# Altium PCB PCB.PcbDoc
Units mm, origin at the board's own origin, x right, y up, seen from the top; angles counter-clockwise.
Board outline 152.4 x 101.6 mm, 2 copper layers (Top Layer, Bottom Layer); 28 components, 28 nets, 134 pads, 40 vias.
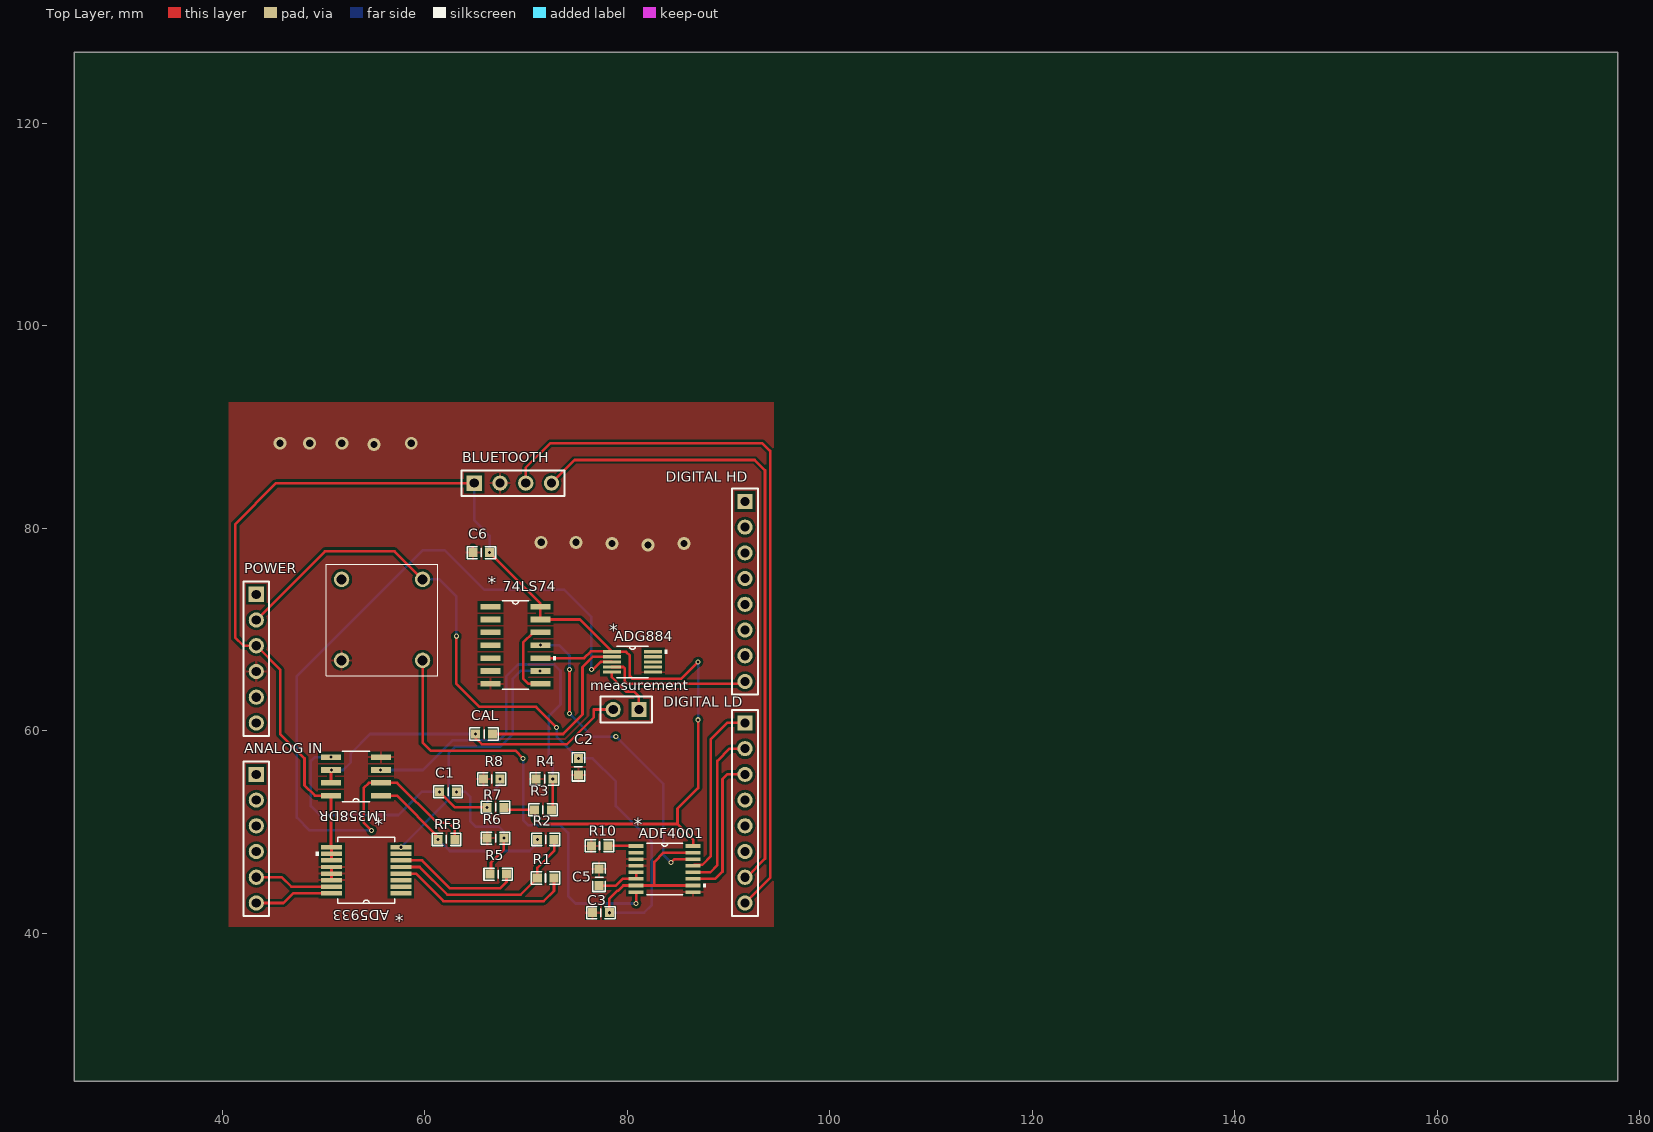
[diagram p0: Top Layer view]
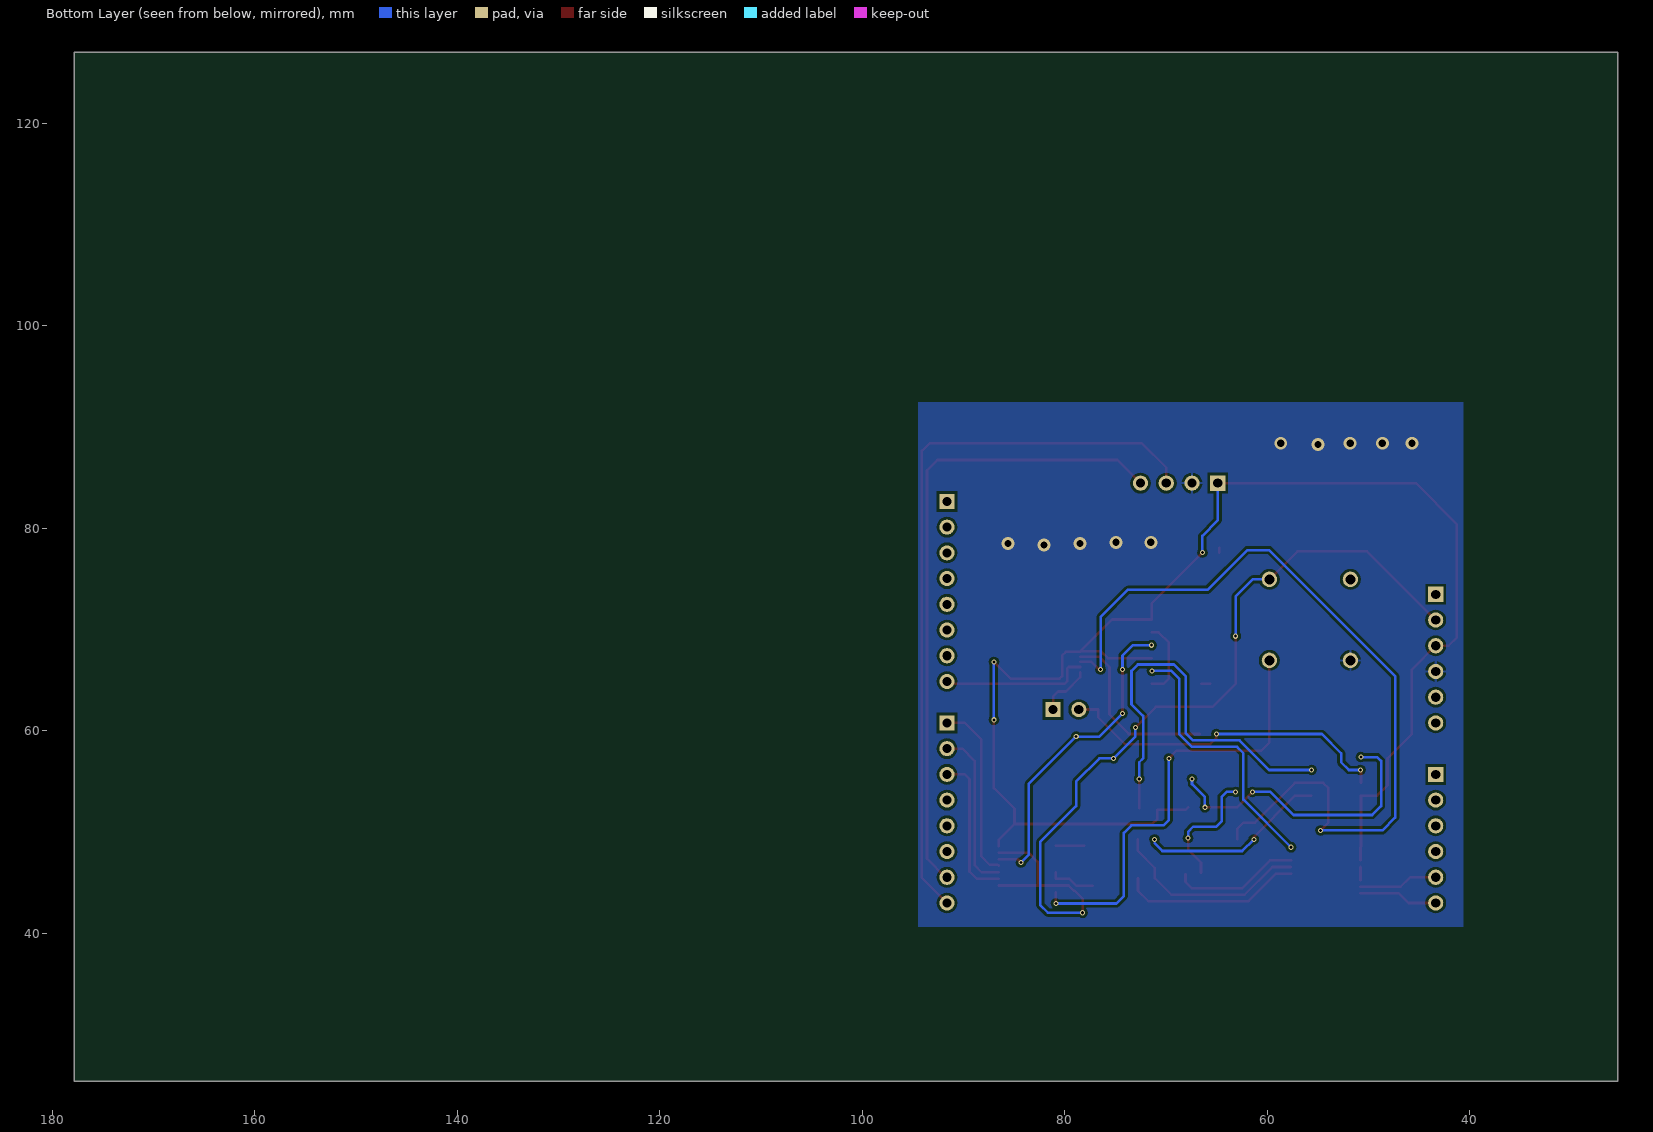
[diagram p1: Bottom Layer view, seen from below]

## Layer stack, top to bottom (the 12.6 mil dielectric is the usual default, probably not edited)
Top Solder: solder mask 0.0102, Solder Resist, Dk 3.5
Top Layer: signal copper 0.0356
Dielectric 1: dielectric 0.32, FR-4, Dk 4.8
Bottom Layer: signal copper 0.0356
Bottom Solder: solder mask 0.0102, Solder Resist, Dk 3.5

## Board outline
25.4,25.4 177.8,25.4 177.8,127 25.4,127

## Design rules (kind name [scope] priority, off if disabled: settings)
Clearance [All] p1: gap=0.254
PolygonConnect [All] p1: connectstyle=Relief reliefconductorwidth=0.254 reliefentries=4 polygonreliefangle="90 Angle" airgapwidth=0.254
RoutingVias [All] p1: holewidth=0.711 width=1.27 viastyle="Through Hole" minholewidth=0.711 minwidth=1.27 maxholewidth=0.711 maxwidth=1.27
SolderMaskExpansion [All] p1: expansion=0.102
Width [All] p1: maxlimit=0.254 minlimit=0.254 preferedwidth=0.254
29 further rules are at their usual default settings.

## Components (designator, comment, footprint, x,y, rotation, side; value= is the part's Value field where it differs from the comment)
74LS74 "SN74LS74A_D_14" D14 68.961,68.453 r0 top
AD5933 "AD5933YRSZ" RS_16 54.229,46.228 r180 top
ADF4001 "ADF4001BRUZ" RU_16 83.693,46.355 r0 top
ADG884 "ADG884BRMZ" RM_10 80.518,66.802 r0 top
"ANALOG IN" "MHDR1X6" "XH2.54Z P6" 43.37,55.7 r270 top
BLUETOOTH "MHDR1X4" "XH2.54Z P4" 64.897,84.455 r0 top
C1 "Cap Pol1" 0603 61.468,53.975 r0 top
C2 "Cap Pol1" 0603 75.184,57.277 r270 top
C3 "Cap Pol1" 0603 78.232,42.037 r180 top
C5 "Cap Pol1" 0603 77.216,44.704 r90 top
C6 "Cap Pol1" 0603 66.421,77.597 r180 top
CAL "Res3" 0603 65.024,59.69 r0 top (schematic designator R9)
"DIGITAL HD" "MHDR1X8" "XH2.54Z P8" 91.63,82.652 r270 top
"DIGITAL LD" "MHDR1X8" "XH2.54Z P8" 91.63,60.78 r270 top
LM358DR "LM358_D_8" D8 53.213,55.499 r180 top
measurement "PROBE" "XH2.54Z P2" 81.153,62.103 r180 top
POWER "MHDR1X6" "XH2.54Z P6" 43.37,73.48 r270 top
R1 "Res3" 0603 72.771,45.466 r180 top
R2 "Res3" 0603 71.12,49.276 r0 top
R3 "Res3" 0603 72.517,52.197 r180 top
R4 "Res3" 0603 70.993,55.245 r0 top
R5 "Res3" 0603 66.421,45.847 r0 top
R6 "Res3" 0603 66.167,49.403 r0 top
R7 "Res3" 0603 66.167,52.451 r0 top
R8 "Res3" 0603 65.786,55.245 r0 top
R10 "Res3" 0603 78.105,48.641 r180 top
RFB "Res3" 0603 62.992,49.276 r180 top
? "CRYSTAL" CRYSTAL 50.292,76.454 r270 top

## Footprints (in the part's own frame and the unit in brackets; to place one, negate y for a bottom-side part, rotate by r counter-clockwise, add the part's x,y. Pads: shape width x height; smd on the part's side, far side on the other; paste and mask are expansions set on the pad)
0603 [mil]
  rect 35x35 smd: 1(0.27,0) 2(65.27,0)
  silkscreen extent -22,-24 88,24
CRYSTAL [mm] "2.048MHz"
  round 1.524 hole 1: 1(1.5,9.5) 2(1.5,1.5) 3(9.5,1.5) 4(9.5,9.5)
  silkscreen extent 0,0 11,11
D8 [mil]
  rect 78x22 smd: 1(-97,75) 2(-97,25) 3(-97,-25) 4(-97,-75) 5(97,-75) 6(97,-25) 7(97,25) 8(97,75)
  silkscreen extent -54,-98 54,98
D14 [mil]
  rect 78x22 smd: 1(-97,150) 2(-97,100) 3(-97,50) 4(-97,0) 5(-97,-50) 6(-97,-100) 7(-97,-150) 8(97,-150) 9(97,-100) 10(97,-50) 11(97,0) 12(97,50) 13(97,100) 14(97,150)
  silkscreen extent -51,-172 156,172
RM_10 [mil]
  rect 70x13 smd mask+4: 1(-80.5,39.37) 2(-80.5,19.68) 3(-80.5,0) 4(-80.5,-19.68) 5(-80.5,-39.37) 6(80.5,-39.37) 7(80.5,-19.68) 8(80.5,0) 9(80.5,19.68) 10(80.5,39.37)
  silkscreen extent -61,-61 136,61
RS_16 [mil]
  rect 81x17 smd: 1(-135,89.57) 2(-135,63.98) 3(-135,38.39) 4(-135,12.8) 5(-135,-12.8) 6(-135,-38.39) 7(-135,-63.98) 8(-135,-89.57) 9(135,-89.57) 10(135,-63.98) 11(135,-38.39) 12(135,-12.8) 13(135,12.8) 14(135,38.39) 15(135,63.98) 16(135,89.57)
  silkscreen extent -110,-128 196,128
RU_16 [mil]
  rect 58x14 smd mask+4: 1(-111,89.57) 2(-111,63.98) 3(-111,38.39) 4(-111,12.8) 5(-111,-12.8) 6(-111,-38.39) 7(-111,-63.98) 8(-111,-89.57) 9(111,-89.57) 10(111,-63.98) 11(111,-38.39) 12(111,-12.8) 13(111,12.8) 14(111,38.39) 15(111,63.98) 16(111,89.57)
  silkscreen extent -70,-100 160,100
"XH2.54Z P2" [mm] "Connector; Header; 6 Position"
  rect 1.5x1.5 hole 0.9: 1(0,0)
  round 1.5 hole 0.9: 2(2.54,0)
  silkscreen extent -1.27,-1.27 3.81,1.27
"XH2.54Z P4" [mm] "Connector; Header; 6 Position"
  rect 1.5x1.5 hole 0.9: 1(0,0)
  round 1.5 hole 0.9: 2(2.54,0) 3(5.08,0) 4(7.62,0)
  silkscreen extent -1.27,-1.27 8.89,1.27
"XH2.54Z P6" [mm] "Connector; Header; 6 Position"
  rect 1.5x1.5 hole 0.9: 1(0,0)
  round 1.5 hole 0.9: 2(2.54,0) 3(5.08,0) 4(7.62,0) 5(10.16,0) 6(12.7,0)
  silkscreen extent -1.27,-1.27 13.97,1.27
"XH2.54Z P8" [mm] "Connector; Header; 6 Position"
  rect 1.5x1.5 hole 0.9: 1(0,0)
  round 1.5 hole 0.9: 2(2.54,0) 3(5.08,0) 4(7.62,0) 5(10.16,0) 6(12.7,0) 7(15.24,0) 8(17.78,0)
  silkscreen extent -1.27,-1.27 19.05,1.27

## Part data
74LS74 AD5933 ADF4001 ADG884 LM358DR: "Imported"
"ANALOG IN" POWER: "Header, 6-Pin"
BLUETOOTH: "Header, 4-Pin"
C1 C2 C3 C5 C6: "Polarized Capacitor (Radial)"
CAL R1 R2 R3 R4 R5 R6 R7 R8 R10 RFB: "Resistor"
"DIGITAL HD" "DIGITAL LD": "Header, 8-Pin"
measurement: library part MHDR1X2, "Header, 2-Pin"

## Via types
v1: diameter 0.5, hole 0.3, Top Layer to Bottom Layer, 30 vias
v2: diameter 1.27, hole 0.711, Top Layer to Bottom Layer, 10 vias

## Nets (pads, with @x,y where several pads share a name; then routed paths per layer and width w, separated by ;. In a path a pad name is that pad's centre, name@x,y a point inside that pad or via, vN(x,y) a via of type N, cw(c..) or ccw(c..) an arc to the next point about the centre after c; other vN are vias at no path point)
GND: 74LS74.7 ?.3 AD5933.12 AD5933.13 AD5933.14 ADF4001.3 ADF4001.4 ADF4001.9 ADG884.6 BLUETOOTH.2 C2.2 C3.2 C5.2 C6.2 LM358DR.4 POWER.4 R4.1 R6.1 R8.1 R10.2 | length 3.7
  Top Layer w0.254: POWER.4@42.873,65.86 POWER.4 ; AD5933.14 AD5933.13 AD5933.12 ; ?.3 ?.3@52.349,66.954 ; C6.2 64.763,78.098 ; 74LS74.7@65.659,64.643 74LS74.7
  other v2: 82.042,78.359 78.486,78.486 85.598,78.486 71.501,78.613 74.93,78.613 54.991,88.265 45.72,88.392 48.641,88.392 51.816,88.392 58.674,88.392
Net74LS74_8: 74LS74.8 74LS74.12 | length 7.6
  Top Layer w0.254: 74LS74.8 70.231,64.643 69.723,65.151 69.723,68.707 70.739,69.723 74LS74.12
Net74LS74_9: 74LS74.9 AD5933.8 | length 26.8
  Bottom Layer w0.254: v1(57.658,48.503) 62.357,53.202 62.357,57.785 62.992,58.42 67.437,58.42 68.707,59.69 68.707,65.151 69.469,65.913 v1(71.374,65.913)
Net74LS74_11: 74LS74.11 ADF4001.14 | length 31.6
  Top Layer w0.254: v1(74.295,61.722) v1(74.295,66.04) ; v1(84.328,46.99) 84.668,47.33 ADF4001.14
  Bottom Layer w0.254: v1(71.425,68.453) 73.279,68.453 74.295,67.437 v1(74.295,66.04) ; v1(74.295,61.722) 76.581,59.436 v1(78.867,59.436) 83.566,54.737 83.566,47.752 v1(84.328,46.99)
Net_1: ?.1 ADF4001.7 ADF4001.10 ADF4001.15 C2.1 C3.1 POWER.2 | length 88.2
  Top Layer w0.254: POWER.2 50.154,77.724 57.022,77.724 ?.1 ; v1(63.119,69.342) 63.119,64.643 65.405,62.357 70.993,62.357 v1(73.025,60.325) ; C3.1 78.225,43.427 79.001,44.203 79.084,44.203 79.611,44.73 ADF4001.7 82.677,44.73 ; ADF4001.10 82.677,44.73 ; ADF4001.15 83.592,47.98 82.677,47.065 82.677,44.73
  Bottom Layer w0.254: ?.1 61.444,74.954 63.119,73.279 v1(63.119,69.342) ; v1(73.025,60.325) 73.025,59.436 v1(75.184,57.277) 76.581,57.277 78.867,54.991 78.867,52.578 82.423,49.022 82.423,42.799 81.661,42.037 v1(78.232,42.037)
Net_4: ?.4 ADF4001.8 | length 44.1
  Top Layer w0.254: ?.4 59.792,58.826 60.579,58.039 68.961,58.039 v1(69.723,57.277) ; v1(80.874,42.951) ADF4001.8
  Bottom Layer w0.254: v1(69.723,57.277) 69.723,51.181 70.231,50.673 73.406,50.673 74.168,49.911 74.168,43.688 74.905,42.951 v1(80.874,42.951)
NetAD5933_4: AD5933.4 R1.1 | length 17.9
  Top Layer w0.254: AD5933.4 59.126,45.903 61.849,43.18 71.755,43.18 72.764,44.189 R1.1
NetAD5933_5: AD5933.5 R1.2 R2.2 | length 19.8
  Top Layer w0.254: AD5933.5 59.492,46.553 62.23,43.815 69.462,43.815 R1.2 71.113,46.475 72.778,48.14 R2.2
NetAD5933_6: AD5933.6 R5.2 | length 12.6
  Top Layer w0.254: AD5933.6 59.731,47.203 62.484,44.45 67.437,44.45 68.079,45.092 R5.2
NetAD5933_15: "ANALOG IN.5" AD5933.15 | length 7.8
  Top Layer w0.254: 43.37,45.54 45.9,45.54 46.837,44.603 AD5933.15
NetAD5933_16: "ANALOG IN.6" AD5933.16 | length 7.8
  Top Layer w0.254: 43.37,43 46.048,43 47.001,43.953 AD5933.16
NetADF4001_1: ADF4001.1 R10.1 | length 2.8
  Top Layer w0.254: R10.1 ADF4001.1@80.863,48.641
NetADF4001_5: ADF4001.5 ADF4001.6 C5.1 | length 4.6
  Top Layer w0.254: C5.1 78.874,44.711 79.543,45.38 ADF4001.6 ADF4001.5
NetADF4001_11: "DIGITAL LD.3" ADF4001.11 | length 14.7
  Top Layer w0.254: ADF4001.11 88.687,45.38 89.408,46.101 89.408,55.245 89.863,55.7 91.63,55.7
NetADF4001_12: "DIGITAL LD.2" ADF4001.12 | length 16.2
  Top Layer w0.254: ADF4001.12 88.194,46.03 88.9,46.736 88.9,57.023 90.117,58.24 91.63,58.24
NetADF4001_13: "DIGITAL LD.1" ADF4001.13 | length 17.7
  Top Layer w0.254: ADF4001.13 86.604,46.771 87.407,46.771 88.265,47.629 88.265,59.182 89.863,60.78 91.63,60.78
NetADG884_2: ADG884.2 CAL.2 | length 17.7
  Top Layer w0.254: CAL.2 73.66,59.69 75.581,61.611 75.581,66.294 76.589,67.302 ADG884.2
NetADG884_3: ADG884.3 LM358DR.2 RFB.1 | length 83
  Top Layer w0.254: v1(54.737,50.165) 53.975,50.927 53.975,54.356 54.483,54.864 LM358DR.2 57.277,54.864 61.214,50.927 62.357,50.927 62.985,50.299 RFB.1 ; v1(76.454,66.04) 76.618,66.04 77.372,66.794 ; 77.38,66.802 ADG884.3
  Bottom Layer w0.254: v1(54.737,50.165) 48.641,50.165 47.371,51.435 47.371,65.405 59.817,77.851 61.976,77.851 65.913,73.914 73.787,73.914 76.454,71.247 v1(76.454,66.04)
NetADG884_4: "DIGITAL HD.8" ADG884.4 | length 14.7
  Top Layer w0.254: ADG884.4 79.621,66.302 79.756,66.167 79.756,64.897 80.01,64.643 91.401,64.643 91.63,64.872
NetADG884_5: ADG884.5 measurement.1 | length 5.3
  Top Layer w0.254: ADG884.5 78.473,65.291 79.883,63.881 80.645,63.881 81.153,63.373 measurement.1
NetBLUETOOTH_3: "DIGITAL LD.8" BLUETOOTH.3 | length 72.6
  Top Layer w0.254: BLUETOOTH.3 69.977,85.979 72.39,88.392 93.345,88.392 94.107,87.63 94.107,45.477 91.63,43
NetBLUETOOTH_4: "DIGITAL LD.7" BLUETOOTH.4 | length 63.4
  Top Layer w0.254: BLUETOOTH.4 74.803,86.741 92.583,86.741 93.599,85.725 93.599,47.371 91.768,45.54
NetC1_1: C1.1 LM358DR.5 R7.1 R8.2 | length 29.3
  Top Layer w0.254: v1(61.475,53.975) 62.999,52.451 v1(66.167,52.451) R7.1
  Bottom Layer w0.254: v1(50.749,57.404) 49.149,57.404 48.768,57.023 48.768,52.578 49.657,51.689 57.404,51.689 59.69,53.975 v1(61.475,53.975) ; v1(66.167,52.451) 66.167,53.467 67.437,54.737 v1(67.437,55.245)
NetC1_2: C1.2 R5.1 R6.2 | length 12.3
  Top Layer w0.254: R5.1@66.548,45.967 66.548,46.99 67.825,48.267 v1(67.825,49.403)
  Bottom Layer w0.254: v1(63.126,53.975) 64.008,53.975 64.516,53.467 64.516,51.054 65.024,50.546 67.31,50.546 67.825,50.031 v1(67.825,49.403)
NetLM358DR_1: LM358DR.1 R2.1 RFB.2 | length 18.2
  Top Layer w0.254: LM358DR.1 57.277,53.594 61.334,49.537 v1(61.334,49.276)
  Bottom Layer w0.254: v1(61.334,49.276) 62.477,48.133 70.358,48.133 71.127,48.902
  other v1: 71.127,49.276
NetLM358DR_3: LM358DR.3 R3.1 R4.2 | length 39.9
  Top Layer w0.254: R3.1@72.651,52.338 R4.2
  Bottom Layer w0.254: v1(55.626,56.134) 59.817,56.134 62.738,59.055 67.354,59.055 68.072,59.773 68.072,65.405 69.215,66.548 72.771,66.548 73.406,65.913 73.406,62.611 72.263,61.468 72.263,57.277 72.644,56.896 v1(72.644,55.245)
NetLM358DR_6: CAL.1 LM358DR.6 LM358DR.7 measurement.2 | length 33.6
  Top Layer w0.254: LM358DR.7 LM358DR.6 ; CAL.1 65.031,59.302 65.659,58.674 74.041,58.674 76.708,61.341 76.708,62.103 measurement.2
  Bottom Layer w0.254: v1(50.8,56.134) 51.943,56.134 52.705,56.896 52.705,57.785 54.61,59.69 v1(65.024,59.69)
VCC: 74LS74.10 74LS74.13 74LS74.14 AD5933.9 AD5933.10 AD5933.11 ADF4001.16 ADG884.1 BLUETOOTH.1 C6.1 LM358DR.8 POWER.3 R3.2 R7.2 | length 145.4
  Top Layer w0.254: AD5933.9@50.749,48.554 LM358DR.8 49.149,53.594 48.133,54.61 48.133,57.277 45.72,59.69 45.72,66.05 POWER.3 42.09,68.4 41.275,69.215 41.275,80.391 45.339,84.455 BLUETOOTH.1 ; AD5933.11 AD5933.10 AD5933.9 ; v1(66.414,77.597) 71.425,72.586 74LS74.14 74LS74.13 75.328,70.993 78.473,67.848 76.417,67.848 75.752,67.183 74LS74.10 ; R7.2 68.079,52.197 R3.2 70.859,51.315 71.374,50.8 84.963,50.8 ; ADG884.1 79.899,67.802 80.264,67.437 80.264,65.405 80.518,65.151 85.344,65.151 v1(86.995,66.802) ; ADF4001.16 86.512,49.251 84.963,50.8 ; v1(86.995,61.091) 86.995,54.356 84.963,52.324 84.963,50.8
  Bottom Layer w0.254: BLUETOOTH.1 64.897,80.772 66.414,79.255 v1(66.414,77.597) ; v1(86.995,61.091) v1(86.995,66.802)
pads on no net: 74LS74.1 74LS74.2 74LS74.3 74LS74.4 74LS74.5 74LS74.6 "ANALOG IN.1" "ANALOG IN.2" "ANALOG IN.3" "ANALOG IN.4" "DIGITAL HD.1" "DIGITAL HD.2" "DIGITAL HD.3" "DIGITAL HD.4" "DIGITAL HD.5" "DIGITAL HD.6" "DIGITAL HD.7" "DIGITAL LD.4" "DIGITAL LD.5" "DIGITAL LD.6" ?.2 AD5933.1 AD5933.2 AD5933.3 AD5933.7 ADF4001.2 ADG884.7 ADG884.8 ADG884.9 ADG884.10 POWER.1 POWER.5 POWER.6

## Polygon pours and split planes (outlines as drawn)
GND on Top Layer "Bottom Layer-No Net" (solid, remove dead copper, pour order 2): 40.64,92.456 40.64,40.64 94.488,40.64 94.488,92.456 40.64,92.456
GND on Bottom Layer "Bottom Layer-No Net" (solid, remove dead copper, pour order 4): 40.64,92.456 40.64,40.64 94.488,40.64 94.488,92.456

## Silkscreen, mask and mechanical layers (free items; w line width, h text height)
Mechanical 1:
  lines w0.254: 40,40 40,93 95,93 95,40 40,40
